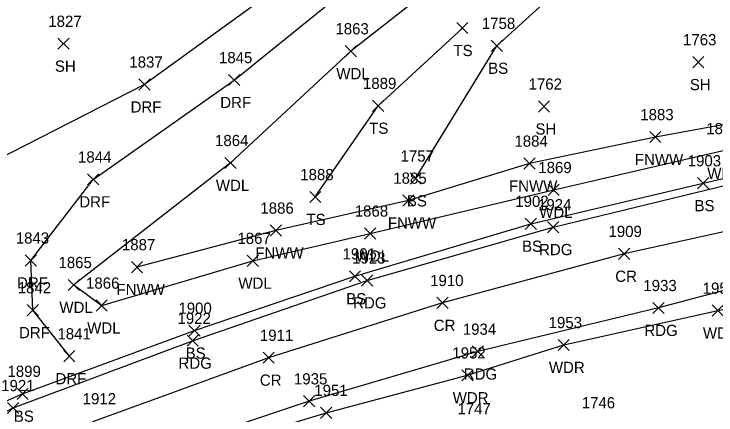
# Model space of a CAD drawing. Extents: x 1621633 to 1624015, y 417863 to 420979.
# Drawn here: x 1621766.2 to 1621891.2, y 418051.2 to 418122.7 of the extents above; entities that cross this region are included whole.
import ezdxf

# ---------------------------------------------------------------- set-up
doc = ezdxf.new("R2010")
doc.units = 0
for name, color, linetype in [('L_A', 7, 'Continuous'), ('L_I', 7, 'Continuous'), ('L_TIC', 7, 'Continuous'), ('LAWA', 7, 'Continuous'), ('LELB', 7, 'Continuous'), ('LFNC', 7, 'Continuous'), ('P_A', 7, 'Continuous'), ('P_I', 7, 'Continuous'), ('P_TIC', 7, 'Continuous'), ('PEU', 7, 'Continuous'), ('PRC', 7, 'Continuous'), ('R_A', 7, 'Continuous'), ('R_I', 7, 'Continuous'), ('R_TIC', 7, 'Continuous'), ('RDF', 7, 'Continuous')]:
    doc.layers.add(name, color=color, linetype=linetype)

msp = doc.modelspace()

# ---------------------------------------------------------------- linework, layer by layer
at = {"layer": 'L_TIC'}
for points in [[(1621845.05, 418119.19), (1621847.05, 418121.19)], [(1621847.05, 418119.19), (1621845.05, 418121.19)], [(1621773.96, 418116.4), (1621775.96, 418118.4)], [(1621775.96, 418116.4), (1621773.96, 418118.4)], [(1621825.17, 418115.06), (1621827.17, 418117.06)], [(1621827.17, 418115.06), (1621825.17, 418117.06)], [(1621851.21, 418116.02), (1621853.21, 418118.02)], [(1621853.21, 418116.02), (1621851.21, 418118.02)], [(1621887.11, 418113.11), (1621889.11, 418115.11)], [(1621889.11, 418113.11), (1621887.11, 418115.11)], [(1621830.04, 418105.33), (1621832.04, 418107.33)], [(1621832.04, 418105.33), (1621830.04, 418107.33)], [(1621859.59, 418105.2), (1621861.59, 418107.2)], [(1621861.59, 418105.2), (1621859.59, 418107.2)], [(1621879.44, 418099.76), (1621881.44, 418101.76)], [(1621881.44, 418099.76), (1621879.44, 418101.76)], [(1621803.72, 418095.14), (1621805.72, 418097.14)], [(1621805.72, 418095.14), (1621803.72, 418097.14)], [(1621857.02, 418095.03), (1621859.02, 418097.03)], [(1621859.02, 418095.03), (1621857.02, 418097.03)], [(1621836.73, 418092.38), (1621838.73, 418094.38)], [(1621838.73, 418092.38), (1621836.73, 418094.38)], [(1621887.98, 418091.53), (1621889.98, 418093.53)], [(1621889.98, 418091.53), (1621887.98, 418093.53)], [(1621861.33, 418090.33), (1621863.33, 418092.33)], [(1621863.33, 418090.33), (1621861.33, 418092.33)], [(1621818.85, 418089.07), (1621820.85, 418091.07)], [(1621820.85, 418089.07), (1621818.85, 418091.07)], [(1621835.43, 418088.43), (1621837.43, 418090.43)], [(1621837.43, 418088.43), (1621835.43, 418090.43)], [(1621857.25, 418084.3), (1621859.25, 418086.3)], [(1621859.25, 418084.3), (1621857.25, 418086.3)], [(1621811.81, 418083.09), (1621813.81, 418085.09)], [(1621813.81, 418083.09), (1621811.81, 418085.09)], [(1621828.62, 418082.56), (1621830.62, 418084.56)], [(1621830.62, 418082.56), (1621828.62, 418084.56)], [(1621807.71, 418077.7), (1621809.71, 418079.7)], [(1621809.71, 418077.7), (1621807.71, 418079.7)], [(1621787.07, 418076.58), (1621789.07, 418078.58)], [(1621789.07, 418076.58), (1621787.07, 418078.58)], [(1621825.91, 418074.93), (1621827.91, 418076.93)], [(1621827.91, 418074.93), (1621825.91, 418076.93)], [(1621775.82, 418073.39), (1621777.82, 418075.39)], [(1621777.82, 418073.39), (1621775.82, 418075.39)], [(1621780.78, 418069.72), (1621782.78, 418071.72)], [(1621782.78, 418069.72), (1621780.78, 418071.72)], [(1621890.56, 418068.82), (1621892.56, 418070.82)], [(1621892.56, 418068.82), (1621890.56, 418070.82)], [(1621797.3, 418065.25), (1621799.3, 418067.25)], [(1621799.3, 418065.25), (1621797.3, 418067.25)], [(1621863.11, 418062.69), (1621865.11, 418064.69)], [(1621865.11, 418062.69), (1621863.11, 418064.69)], [(1621845.96, 418057.28), (1621847.96, 418059.28)], [(1621847.96, 418057.28), (1621845.96, 418059.28)], [(1621766.69, 418054), (1621768.69, 418056)], [(1621768.69, 418054), (1621766.69, 418056)], [(1621820.8, 418050.6), (1621822.8, 418052.6)], [(1621822.8, 418050.6), (1621820.8, 418052.6)]]:
    msp.add_lwpolyline(points, dxfattribs=at)
at = {"layer": 'LAWA'}
for points in [[(1621956.58, 418284.61), (1621944.79, 418263.74), (1621937.99, 418240.81), (1621923.64, 418212.08), (1621903.11, 418191.44), (1621882.69, 418166.67), (1621873.44, 418154.29), (1621850.99, 418135.57), (1621826.17, 418116.06), (1621804.72, 418096.14), (1621776.82, 418074.39), (1621781.78, 418070.72), (1621808.71, 418078.7), (1621829.62, 418083.56), (1621862.33, 418091.33), (1621892.29, 418098.27), (1621914.93, 418102.81), (1621920.3, 418103.1), (1621927.79, 418103.9), (1621958.83, 418106.15)], [(1621679.19, 417971.6), (1621702.48, 417990.45), (1621715.01, 418000.48), (1621736.64, 418013.96), (1621752.88, 418023.2), (1621756.92, 418025.88), (1621771.11, 418032.08), (1621799.59, 418044.88), (1621821.8, 418051.6), (1621846.96, 418058.28), (1621864.11, 418063.69), (1621891.56, 418069.82), (1621913.25, 418074.11), (1621937.15, 418070.7)]]:
    msp.add_lwpolyline(points, dxfattribs=at)
at = {"layer": 'LELB'}
for points in [[(1621837.73, 418093.38), (1621852.21, 418117.02), (1621868.22, 418131.62), (1621888.03, 418154.29), (1621907.66, 418174.83)], [(1621819.85, 418090.07), (1621831.04, 418106.33), (1621846.05, 418120.19)], [(1621664.03, 417989.43), (1621687.49, 418007.66), (1621711.94, 418024.27), (1621730.31, 418035.53), (1621752.55, 418048.38), (1621767.69, 418055), (1621798.3, 418066.25), (1621826.91, 418075.93), (1621858.25, 418085.3), (1621888.98, 418092.53), (1621914.26, 418098.41), (1621931, 418100.47)]]:
    msp.add_lwpolyline(points, dxfattribs=at)
at = {"layer": 'LFNC'}
msp.add_lwpolyline([(1621964.2, 418111.07), (1621948.53, 418107.92), (1621925.05, 418107.39), (1621910.63, 418106.25), (1621880.44, 418100.76), (1621858.02, 418096.03), (1621836.43, 418089.43), (1621812.81, 418084.09), (1621788.07, 418077.58)], dxfattribs=at)
at = {"layer": 'P_TIC'}
for points in [[(1621861.24, 418083.7), (1621863.24, 418085.7)], [(1621863.24, 418083.7), (1621861.24, 418085.7)], [(1621873.87, 418078.94), (1621875.87, 418080.94)], [(1621875.87, 418078.94), (1621873.87, 418080.94)], [(1621828.1, 418074.2), (1621830.1, 418076.2)], [(1621830.1, 418074.2), (1621828.1, 418076.2)], [(1621841.52, 418070.19), (1621843.52, 418072.19)], [(1621843.52, 418070.19), (1621841.52, 418072.19)], [(1621880, 418069.29), (1621882, 418071.29)], [(1621882, 418069.29), (1621880, 418071.29)], [(1621796.99, 418063.45), (1621798.99, 418065.45)], [(1621798.99, 418063.45), (1621796.99, 418065.45)], [(1621847.82, 418061.51), (1621849.82, 418063.51)], [(1621849.82, 418061.51), (1621847.82, 418063.51)], [(1621810.53, 418060.42), (1621812.53, 418062.42)], [(1621812.53, 418060.42), (1621810.53, 418062.42)], [(1621817.74, 418052.66), (1621819.74, 418054.66)], [(1621819.74, 418052.66), (1621817.74, 418054.66)], [(1621765, 418051.46), (1621767, 418053.46)], [(1621767, 418051.46), (1621765, 418053.46)]]:
    msp.add_lwpolyline(points, dxfattribs=at)
at = {"layer": 'PEU'}
for points in [[(1621666.09, 417987.33), (1621690.6, 418006.33), (1621714.11, 418022.73), (1621739.5, 418038.46), (1621766, 418052.46), (1621797.99, 418064.45), (1621829.1, 418075.2), (1621862.24, 418084.7), (1621894.03, 418092.42)], [(1621912.2, 418078.59), (1621881, 418070.29), (1621848.82, 418062.51), (1621818.74, 418053.66), (1621789.44, 418043.87), (1621760.32, 418029.9), (1621735.43, 418015.46), (1621709.62, 417999.4), (1621686.1, 417982.19), (1621676.52, 417973.9)]]:
    msp.add_lwpolyline(points, dxfattribs=at)
at = {"layer": 'PRC'}
msp.add_lwpolyline([(1621971.07, 418099.34), (1621938.44, 418093.73), (1621906.63, 418086.95), (1621874.87, 418079.94), (1621842.52, 418071.19), (1621811.53, 418061.42), (1621780.51, 418050.11), (1621750.95, 418035.3), (1621723.04, 418018.53), (1621696.18, 418000.53), (1621670.93, 417981.57)], dxfattribs=at)
at = {"layer": 'R_TIC'}
for points in [[(1621804.38, 418109.92), (1621806.38, 418111.92)], [(1621806.38, 418109.92), (1621804.38, 418111.92)], [(1621788.4, 418109.13), (1621790.4, 418111.13)], [(1621790.4, 418109.13), (1621788.4, 418111.13)], [(1621779.25, 418092.21), (1621781.25, 418094.21)], [(1621781.25, 418092.21), (1621779.25, 418094.21)], [(1621768.16, 418077.76), (1621770.16, 418079.76)], [(1621770.16, 418077.76), (1621768.16, 418079.76)], [(1621768.52, 418068.9), (1621770.52, 418070.9)], [(1621770.52, 418068.9), (1621768.52, 418070.9)], [(1621775.02, 418060.68), (1621777.02, 418062.68)], [(1621777.02, 418060.68), (1621775.02, 418062.68)]]:
    msp.add_lwpolyline(points, dxfattribs=at)
at = {"layer": 'RDF'}
for points in [[(1621776.02, 418061.68), (1621769.52, 418069.9), (1621769.16, 418078.76), (1621780.25, 418093.21), (1621805.38, 418110.92), (1621830.45, 418131.22), (1621857.04, 418151.01), (1621883.03, 418174.44), (1621903.81, 418200.1), (1621921.4, 418229.54), (1621932.52, 418258.85), (1621944.51, 418286.74), (1621960.39, 418307.1)], [(1621940.59, 418295.72), (1621925.73, 418267.99), (1621914.41, 418239.65), (1621902.22, 418210.53), (1621883.89, 418186.91), (1621861.02, 418166.16), (1621838.61, 418146.11), (1621813.95, 418127.94), (1621789.4, 418110.13), (1621762.83, 418096.6), (1621756.07, 418081.78), (1621758.54, 418055.77)]]:
    msp.add_lwpolyline(points, dxfattribs=at)

# ---------------------------------------------------------------- texts
at = {"layer": 'L_A'}
for s, p in [('TS', (1621844.46, 418115.19)), ('SH', (1621773.44, 418112.4)), ('BS', (1621850.65, 418112.02)), ('WDL', (1621823.59, 418111.06)), ('SH', (1621886.59, 418109.11)), ('TS', (1621829.45, 418101.33)), ('SH', (1621859.08, 418101.2)), ('FNWW', (1621876.79, 418095.76)), ('WDL', (1621889.7, 418093.27)), ('WDL', (1621802.13, 418091.14)), ('FNWW', (1621854.37, 418091.03)), ('BS', (1621836.17, 418088.38)), ('BS', (1621887.42, 418087.53)), ('WDL', (1621859.75, 418086.33)), ('TS', (1621818.26, 418085.07)), ('FNWW', (1621832.78, 418084.43)), ('BS', (1621856.69, 418080.3)), ('FNWW', (1621809.15, 418079.09)), ('WDL', (1621827.04, 418078.56)), ('WDL', (1621806.13, 418073.7)), ('FNWW', (1621784.42, 418072.58)), ('BS', (1621825.36, 418070.93)), ('WDL', (1621774.24, 418069.39)), ('WDL', (1621779.2, 418065.72)), ('WDR', (1621888.92, 418064.82)), ('BS', (1621796.74, 418061.25)), ('WDR', (1621861.47, 418058.69)), ('WDR', (1621844.33, 418053.28)), ('BS', (1621766.13, 418050))]:
    msp.add_text(s, height=2, dxfattribs=at).set_placement(p)
at = {"layer": 'L_I'}
for s, p in [('1827', (1621772.26, 418120.4)), ('1758', (1621849.52, 418120.02)), ('1863', (1621823.43, 418119.06)), ('1763', (1621885.37, 418117.11)), ('1889', (1621828.34, 418109.33)), ('1762', (1621857.85, 418109.2)), ('1883', (1621877.75, 418103.76)), ('1870', (1621889.51, 418101.27)), ('1864', (1621801.98, 418099.14)), ('1884', (1621855.33, 418099.03)), ('1757', (1621835.04, 418096.38)), ('1903', (1621886.21, 418095.53)), ('1869', (1621859.58, 418094.33)), ('1888', (1621817.16, 418093.07)), ('1885', (1621833.74, 418092.43)), ('1902', (1621855.48, 418088.3)), ('1886', (1621810.06, 418087.09)), ('1868', (1621826.88, 418086.56)), ('1867', (1621805.97, 418081.7)), ('1887', (1621785.38, 418080.58)), ('1901', (1621824.71, 418078.93)), ('1865', (1621774.08, 418077.39)), ('1866', (1621778.99, 418073.72)), ('1954', (1621888.87, 418072.82)), ('1900', (1621795.45, 418069.25)), ('1953', (1621861.42, 418066.69)), ('1952', (1621844.27, 418061.28)), ('1899', (1621764.99, 418058)), ('1951', (1621819.67, 418054.6)), ('1746', (1621867.33, 418052.39)), ('1747', (1621845.17, 418051.32))]:
    msp.add_text(s, height=2, dxfattribs=at).set_placement(p)
at = {"layer": 'P_A'}
for s, p in [('RDG', (1621859.72, 418079.7)), ('CR', (1621873.3, 418074.94)), ('RDG', (1621826.59, 418070.2)), ('CR', (1621840.95, 418066.19)), ('RDG', (1621878.48, 418065.29)), ('RDG', (1621795.47, 418059.45)), ('RDG', (1621846.31, 418057.51)), ('CR', (1621809.96, 418056.42))]:
    msp.add_text(s, height=2, dxfattribs=at).set_placement(p)
at = {"layer": 'P_I'}
for s, p in [('1924', (1621859.54, 418087.7)), ('1909', (1621872.09, 418082.94)), ('1923', (1621826.4, 418078.2)), ('1910', (1621840.31, 418074.19)), ('1933', (1621878.3, 418073.29)), ('1922', (1621795.29, 418067.45)), ('1934', (1621846.13, 418065.51)), ('1911', (1621809.97, 418064.42)), ('1935', (1621816.04, 418056.66)), ('1921', (1621763.87, 418055.46)), ('1912', (1621778.39, 418053.11))]:
    msp.add_text(s, height=2, dxfattribs=at).set_placement(p)
at = {"layer": 'R_A'}
for p in [(1621786.93, 418105.13), (1621802.91, 418105.92), (1621777.79, 418088.21), (1621766.7, 418073.76), (1621767.05, 418064.9), (1621773.55, 418056.68)]:
    msp.add_text('DRF', height=2, dxfattribs=at).set_placement(p)
at = {"layer": 'R_I'}
for s, p in [('1845', (1621802.68, 418113.92)), ('1837', (1621786.71, 418113.13)), ('1844', (1621777.56, 418096.21)), ('1843', (1621766.47, 418081.76)), ('1842', (1621766.82, 418072.9)), ('1841', (1621773.89, 418064.68))]:
    msp.add_text(s, height=2, dxfattribs=at).set_placement(p)

doc.saveas('drawing.dxf')
